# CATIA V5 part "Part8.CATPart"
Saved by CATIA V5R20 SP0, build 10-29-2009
Part number: 3JT9.5X2X13.5
Revision: ANY
Definition: UNKNOWN
Nomenclature: 3JT9.5X2X13.5
Source: Unknown
Bounding box of the stored display mesh (mm): x -6.581 to 6.581, y -1 to 1, z -6.75 to 6.75
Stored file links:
  C:\Users\Utente\Desktop\IO LAVORO\3D X SITO CF\CUMSA\3D files PW\pw081025\pw081025_injection\Part8.CATPart
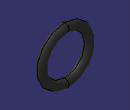
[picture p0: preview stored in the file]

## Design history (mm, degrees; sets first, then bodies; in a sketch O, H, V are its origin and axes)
Body1 "Revolución1" (main body)
  Solid1: solid without history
